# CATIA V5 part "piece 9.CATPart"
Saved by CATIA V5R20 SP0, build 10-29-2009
Part number: piece 9
Bounding box of the stored display mesh (mm): x -13.906 to 46.094, y 0.959 to 29.959, z 0 to 4
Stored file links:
  G:\Khaled_CFAO_2011\SIL\SIL_GR1\blaboucarri\Khaled\CAD_CATIA\piece 9.CATPart
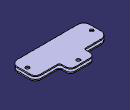
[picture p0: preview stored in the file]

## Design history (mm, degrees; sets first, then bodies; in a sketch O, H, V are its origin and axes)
Parameters
  `tiers de longueur` = 20 mm
  largeur = 20 mm
  epaisseur = 4 mm
  `rayon trou` = 1.5 mm
  `distance trou bord` = 2 mm
  `largeur poche` = 2 mm
  `profondeur poche` = 27 mm
  `largeur surélevée` = 9 mm
  `distance poche bord` = 1 mm
Body1 (main body)
  Sketch1 on xy-plane, origin (0, 0, 0), H (1, 0, 0), V (0, 1, 0)
    line L1 (-8.8741, 0.9593) -> (40.6572, 0.9593)
    point P1 (46.0936, 0.9593)
    line L2 (46.0936, 6.3956) -> (46.0936, 16.32)
    point P2 (46.0936, 20.9593)
    line L3 (41.4543, 20.9593) -> (27.9631, 20.9593)
    point P3 (26.0936, 20.9593)
    line L4 (26.0936, 22.8288) -> (26.0936, 26.1257)
    point P4 (26.0936, 29.9593)
    line L5 (22.26, 29.9593) -> (10.0154, 29.9593)
    point P5 (6.0936, 29.9593)
    line L6 (6.0936, 26.0374) -> (6.0936, 22.6824)
    point P6 (6.0936, 20.9593)
    line L7 (4.3704, 20.9593) -> (-8.1337, 20.9593)
    point P7 (-13.9064, 20.9593)
    line L8 (-13.9064, 15.1865) -> (-13.9064, 5.9916)
    circle A1 centre (16.0936, 26.4593) radius 1.5
    point P8 (16.0936, 26.4593)
    circle A2 centre (42.5936, 10.9593) radius 1.5
    point P9 (42.5936, 10.9593)
    circle A3 centre (-10.4064, 10.9593) radius 1.5
    point P10 (-10.4064, 10.9593)
    arc A4 centre (41.4543, 16.32) radius 4.6393 from (41.4543, 20.9593) to (46.0936, 16.32) cw
    arc A5 centre (40.6572, 6.3956) radius 5.4364 from (46.0936, 6.3956) to (40.6572, 0.9593) cw
    arc A6 centre (-8.1337, 15.1865) radius 5.7728 from (-8.1337, 20.9593) to (-13.9064, 15.1865) ccw
    arc A7 centre (-8.8741, 5.9916) radius 5.0323 from (-13.9064, 5.9916) to (-8.8741, 0.9593) ccw
    arc A8 centre (22.26, 26.1257) radius 3.8335 from (22.26, 29.9593) to (26.0936, 26.1257) cw
    arc A9 centre (10.0154, 26.0374) radius 3.9219 from (10.0154, 29.9593) to (6.0936, 26.0374) ccw
    arc A10 centre (27.9631, 22.8288) radius 1.8696 from (26.0936, 22.8288) to (27.9631, 20.9593) ccw
    arc A11 centre (4.3704, 22.6824) radius 1.7231 from (6.0936, 22.6824) to (4.3704, 20.9593) cw
    radius A2 = 1.5 {= `rayon trou`}
    radius A1 = 1.5 {= `rayon trou`}
    radius A3 = 1.5 {= `rayon trou`}
    distance P9 L2 = 3.5 {= `rayon trou` +`distance trou bord`}
    distance P9 L3 = 10 {= largeur /2}
    distance P10 L8 = 3.5 {= `distance trou bord` +`rayon trou`}
    distance P8 L5 = 3.5 {= `distance trou bord` +`rayon trou`}
    distance P8 L4 = 10 {= `tiers de longueur` /2}
    distance L5 L3 = 9 {= `largeur surélevée`}
    distance P10 L7 = 10 {= largeur /2}
    distance P2 P3 = 20 {= `tiers de longueur`}
    distance P1 P2 = 20 {= largeur}
    radius A4 = 4.6393
    radius A5 = 5.4364
    distance P6 P7 = 20 {= `tiers de longueur`}
    radius A6 = 5.7728
    radius A7 = 5.0323
    distance P4 P5 = 20 {= `tiers de longueur`}
    radius A8 = 3.8335
    radius A9 = 3.9219
    radius A10 = 1.8696
    radius A11 = 1.7231
    horizontal: L1 H, L3 H, L5 H, L7 H
    vertical: L2 V, L4 V, L6 V, L8 V
    coincidence: P6 L3, L3 P2, L2 P2, L2 P1, L1 P1, L7 P7, L8 P7, L5 P4, L4 P4, L5 P5, L6 P5, L4 P3, L3 P3, L6 P6, L7 P6
    tangency: A4 L3, A4 L2, A5 L2, A5 L1, A6 L7, A6 L8, A7 L8, A7 L1, A8 L5, A8 L4, A9 L5, A9 L6, A10 L4, A10 L3, A11 L6, A11 L7
  Pad1: profile Sketch1, direction (0, 0, 1), length 4 {= epaisseur}
  Sketch2 on face of Pad1 from Sketch1.L5, origin (0, 29.9593, 0), H (-1, 0, 0), V (0, 0, 1)
    line L1 (-46.0936, 3) -> (13.9064, 3)
    line L2 (13.9064, 3) -> (13.9064, 1)
    line L3 (13.9064, 1) -> (-46.0936, 1)
    line L4 (-46.0936, 1) -> (-46.0936, 3)
    reference projected point E1 (13.9064, 4) from vertex [face of Pad1 from Sketch1.L8 | end face of Pad1 | face of Pad1 from Sketch1.A6]
    reference projected line E2 (8.1337, 4) -> (13.9064, 4) from edge [face of Pad1 from Sketch1.A6 | end face of Pad1]
    distance L2 E1 = 0
    length L1 = 60 {= 3*`tiers de longueur`}
    length L2 = 2 {= `largeur poche`}
    distance L1 E2 = 1 {= `distance poche bord`}
    horizontal: L1 H, L3 H
    vertical: L2 V, L4 V
  Pocket1: profile Sketch2, direction (0, -1, 0), length 27 {= `profondeur poche`}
